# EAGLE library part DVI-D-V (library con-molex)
CONNECTOR MiroCross(TM)-DVI i/0 plug and receptacle connector system (scart)
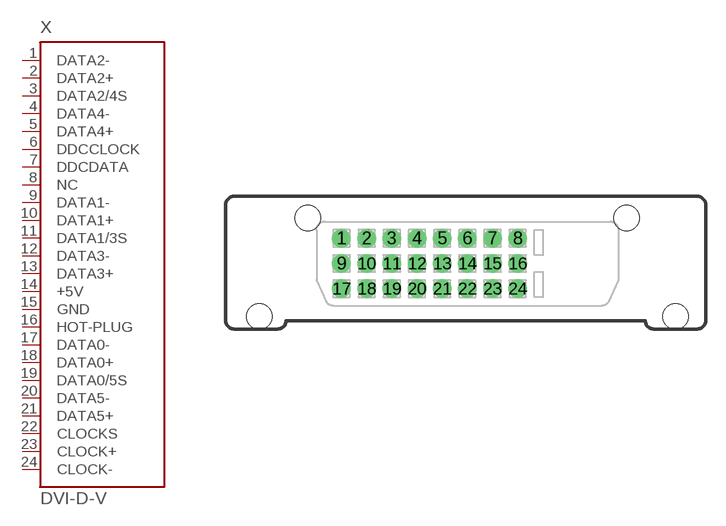
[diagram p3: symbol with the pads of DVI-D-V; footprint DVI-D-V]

Designator prefix X

## DVI-D-V (OC_FARNELL: unknown; OC_NEWARK: unknown)  [DVI-D-V]
1  DATA2-  pas
2  DATA2+  pas
3  DATA2/4S  pas
4  DATA4-  pas
5  DATA4+  pas
6  DDCCLOCK  pas
7  DDCDATA  pas
8  NC  pas
9  DATA1-  pas
10  DATA1+  pas
11  DATA1/3S  pas
12  DATA3-  pas
13  DATA3+  pas
14  +5V  pwr
15  GND  pwr
16  HOT-PLUG  pas
17  DATA0-  pas
18  DATA0+  pas
19  DATA0/5S  pas
20  DATA5-  pas
21  DATA5+  pas
22  CLOCKS  pas
23  CLOCK+  pas
24  CLOCK-  pas

## Footprint DVI-D-V (pad centres in mm)
CONNECTOR MiroCross(TM)-DVI i/0 plug and receptacle connector system (scart)
drill 0.864 pad 1.397 round: 1 -9.525,1.27; 2 -7.62,1.27; 3 -5.715,1.27; 4 -3.81,1.27; 5 -1.905,1.27; 6 0,1.27; 7 1.905,1.27; 8 3.81,1.27; 9 -9.525,-0.635; 10 -7.62,-0.635; 11 -5.715,-0.635; 12 -3.81,-0.635; 13 -1.905,-0.635; 14 0,-0.635; 15 1.905,-0.635; 16 3.81,-0.635; 17 -9.525,-2.54; 18 -7.62,-2.54; 19 -5.715,-2.54; 20 -3.81,-2.54; 21 -1.905,-2.54; 22 0,-2.54; 23 1.905,-2.54; 24 3.81,-2.54
hole 1.93 at -12.065,2.794
hole 1.93 at 12.065,2.794
hole 1.93 at -15.748,-4.648
hole 1.93 at 15.748,-4.648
